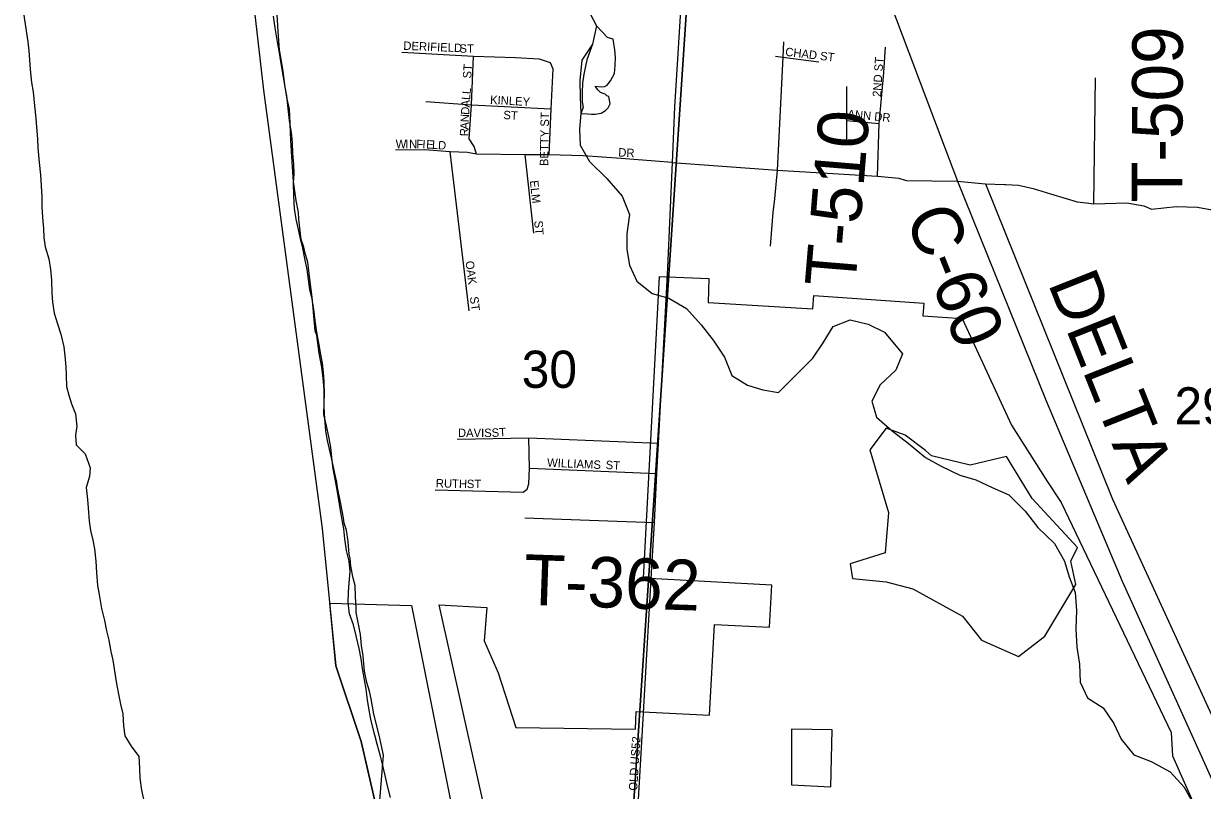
# Model space of a CAD drawing. Extents: x 1949938.81 to 1949945.61, y 152207.65 to 152214.09.
# Drawn here: x 1949939.542 to 1949940.868, y 152210.308 to 152211.171 of the extents above; entities that cross this region are included whole.
import ezdxf

# ---------------------------------------------------------------- set-up
doc = ezdxf.new("R2010")
doc.units = 0
for name, color, linetype in [('GM_X_City_Street', 7, 'Continuous'), ('GM_X_City_Street_Text', 7, 'Continuous'), ('GM_X_Corporation', 7, 'Continuous'), ('GM_X_County', 7, 'Continuous'), ('GM_X_County_Road', 7, 'Continuous'), ('GM_X_County_Road_Text', 7, 'Continuous'), ('GM_X_Major_River', 7, 'Continuous'), ('GM_X_Minor_Lake', 7, 'Continuous'), ('GM_X_Minor_River', 7, 'Continuous'), ('GM_X_Section', 7, 'Continuous'), ('GM_X_Section_Text', 7, 'Continuous'), ('GM_X_Township', 7, 'Continuous'), ('GM_X_Township_Road', 7, 'Continuous'), ('GM_X_Township_Road_Text', 7, 'Continuous'), ('GM_X_Township_Subdivision', 7, 'Continuous'), ('GM_X_Township_Subdivision_Text', 7, 'Continuous'), ('GM_X_US_Route', 7, 'Continuous')]:
    doc.layers.add(name, color=color, linetype=linetype)

msp = doc.modelspace()

# ---------------------------------------------------------------- linework, layer by layer
at = {"layer": 'GM_X_City_Street'}
msp.add_lwpolyline([(1949940.2381, 152210.3883), (1949940.2314, 152210.2719), (1949940.2281, 152210.2175)], dxfattribs=at)
at = {"layer": 'GM_X_Corporation'}
msp.add_lwpolyline([(1949940.0909, 152210.1498), (1949940.0091, 152210.5167), (1949940.0628, 152210.5138), (1949940.0597, 152210.4762), (1949940.0757, 152210.4401), (1949940.0953, 152210.3788), (1949940.2298, 152210.3768), (1949940.2308, 152210.3968), (1949940.3132, 152210.3927), (1949940.3187, 152210.4946), (1949940.3808, 152210.4915), (1949940.3834, 152210.5389), (1949940.2388, 152210.5466), (1949940.2569, 152210.8861), (1949940.3123, 152210.8839), (1949940.3118, 152210.857), (1949940.4294, 152210.8497), (1949940.4305, 152210.8648), (1949940.5542, 152210.8564), (1949940.5531, 152210.8419), (1949940.5973, 152210.8391), (1949940.6527, 152210.719), (1949940.6932, 152210.6552), (1949940.7087, 152210.632), (1949940.8323, 152210.3731), (1949940.8339, 152210.3468), (1949940.8851, 152210.231)], dxfattribs=at)
for points in [[(1949940.5118, 152210.7154), (1949940.4935, 152210.6912), (1949940.5147, 152210.6207), (1949940.5109, 152210.5753), (1949940.4713, 152210.5628), (1949940.4742, 152210.5463), (1949940.5118, 152210.5425), (1949940.5418, 152210.5347), (1949940.5978, 152210.5038), (1949940.619, 152210.4768), (1949940.6606, 152210.4584), (1949940.6905, 152210.4816), (1949940.7253, 152210.5396), (1949940.7195, 152210.5657), (1949940.7272, 152210.5811), (1949940.676, 152210.6362), (1949940.6472, 152210.6836), (1949940.6065, 152210.6739), (1949940.563, 152210.6845), (1949940.5563, 152210.6903), (1949940.5331, 152210.7077)], [(1949939.8861, 152210.5185), (1949939.9781, 152210.5158), (1949940.0249, 152210.2816), (1949940.1348, 152209.9064), (1949940.0387, 152209.8948), (1949939.9388, 152210.288), (1949939.9215, 152210.363), (1949939.8931, 152210.4482)], [(1949940.4054, 152210.3769), (1949940.4054, 152210.314), (1949940.4495, 152210.3118), (1949940.451, 152210.3762)]]:
    msp.add_lwpolyline(points, close=True, dxfattribs=at)
at = {"layer": 'GM_X_County'}
msp.add_lwpolyline([(1949939.7311, 152211.8376), (1949939.7258, 152211.7457), (1949939.7413, 152211.6273), (1949939.7962, 152211.2639), (1949939.7977, 152211.2171), (1949939.8117, 152211.0959), (1949939.8776, 152210.6025), (1949939.8931, 152210.4482), (1949939.9215, 152210.363), (1949939.9378, 152210.2911), (1949940.0851, 152209.7125), (1949940.1207, 152209.6209), (1949940.3383, 152209.2145), (1949940.3947, 152209.1158)], dxfattribs=at)
at = {"layer": 'GM_X_County_Road'}
for points in [[(1949940.0902, 152211.8474), (1949940.1245, 152211.7264), (1949940.1446, 152211.6586), (1949940.1553, 152211.6171), (1949940.1779, 152211.5675), (1949940.2141, 152211.4924), (1949940.2747, 152211.3627), (1949940.2807, 152211.3456), (1949940.2832, 152211.3349), (1949940.2845, 152211.32), (1949940.2871, 152211.2866), (1949940.2865, 152211.2628), (1949940.2824, 152211.2159), (1949940.2737, 152211.0767), (1949940.2714, 152211.0147), (1949940.2658, 152210.896)], [(1949940.6238, 152210.9905), (1949940.7663, 152210.6357), (1949940.884, 152210.3789), (1949940.9129, 152210.3457), (1949940.9292, 152210.3083), (1949940.9485, 152210.2329)], [(1949940.2658, 152210.896), (1949940.2627, 152210.8322), (1949940.2555, 152210.6987), (1949940.2536, 152210.6646), (1949940.2509, 152210.6092), (1949940.248, 152210.559)], [(1949940.248, 152210.559), (1949940.2393, 152210.4083)], [(1949940.2393, 152210.4083), (1949940.2381, 152210.3883)]]:
    msp.add_lwpolyline(points, dxfattribs=at)
at = {"layer": 'GM_X_Major_River'}
for points in [[(1949939.5418, 152211.1828), (1949939.5437, 152211.1703), (1949939.5452, 152211.16), (1949939.5467, 152211.1505), (1949939.5478, 152211.1403), (1949939.5486, 152211.13), (1949939.5493, 152211.1194), (1949939.5508, 152211.1046), (1949939.5524, 152211.0939), (1949939.5539, 152211.0784), (1949939.5554, 152211.0643), (1949939.5565, 152211.0544), (1949939.5576, 152211.0411), (1949939.558, 152211.0309), (1949939.5595, 152211.0146), (1949939.5607, 152211.0005), (1949939.5614, 152210.9883), (1949939.5622, 152210.9758), (1949939.5622, 152210.9652), (1949939.5629, 152210.9526), (1949939.5641, 152210.9401), (1949939.5644, 152210.9302), (1949939.5659, 152210.9196), (1949939.5701, 152210.9063), (1949939.572, 152210.8941), (1949939.5731, 152210.8823), (1949939.5735, 152210.8675), (1949939.5742, 152210.8573), (1949939.5761, 152210.8451), (1949939.5799, 152210.8329), (1949939.5837, 152210.8212), (1949939.5871, 152210.8071), (1949939.5882, 152210.7968), (1949939.5894, 152210.7847), (1949939.5897, 152210.7752), (1949939.5901, 152210.7623), (1949939.5928, 152210.7528), (1949939.5958, 152210.7429)], [(1949939.836, 152211.0992), (1949939.8341, 152211.1105), (1949939.8314, 152211.1261), (1949939.8292, 152211.1402), (1949939.8273, 152211.1504), (1949939.8246, 152211.166), (1949939.8227, 152211.1793)], [(1949939.9546, 152210.3), (1949939.9516, 152210.3114), (1949939.9485, 152210.3247), (1949939.9459, 152210.3357), (1949939.9432, 152210.3463), (1949939.9395, 152210.36), (1949939.9368, 152210.3699), (1949939.9327, 152210.3862), (1949939.9304, 152210.398), (1949939.9285, 152210.4098), (1949939.927, 152210.4216), (1949939.9251, 152210.4322), (1949939.9228, 152210.4452), (1949939.9213, 152210.4558), (1949939.9191, 152210.4676), (1949939.916, 152210.4817), (1949939.913, 152210.4942), (1949939.9085, 152210.5067), (1949939.907, 152210.5189), (1949939.9073, 152210.5315), (1949939.9081, 152210.5413), (1949939.9089, 152210.5543), (1949939.9081, 152210.5657), (1949939.9051, 152210.5778), (1949939.9032, 152210.5911), (1949939.9021, 152210.6022), (1949939.9002, 152210.6124), (1949939.8979, 152210.6253), (1949939.8964, 152210.6348), (1949939.8941, 152210.6481), (1949939.8922, 152210.658), (1949939.89, 152210.6698), (1949939.8888, 152210.6793), (1949939.8873, 152210.6938), (1949939.8851, 152210.7063), (1949939.8824, 152210.7181), (1949939.8794, 152210.731), (1949939.8798, 152210.7443), (1949939.8802, 152210.7538), (1949939.8798, 152210.7679), (1949939.879, 152210.7781), (1949939.8779, 152210.7888), (1949939.876, 152210.7983), (1949939.8741, 152210.8093), (1949939.8715, 152210.8237), (1949939.8696, 152210.8366), (1949939.8681, 152210.8496), (1949939.8662, 152210.8606), (1949939.8639, 152210.8716), (1949939.8624, 152210.883), (1949939.8609, 152210.894), (1949939.8582, 152210.9066), (1949939.856, 152210.918), (1949939.8533, 152210.9286), (1949939.8511, 152210.9392), (1949939.8484, 152210.9506), (1949939.8465, 152210.9628), (1949939.8458, 152210.9772), (1949939.8454, 152210.9913), (1949939.8462, 152211.0019), (1949939.8458, 152211.0125), (1949939.8447, 152211.0247), (1949939.8443, 152211.0369), (1949939.8431, 152211.0479), (1949939.8409, 152211.0619), (1949939.8394, 152211.0752), (1949939.8379, 152211.0897), (1949939.836, 152211.0992)], [(1949939.5958, 152210.7429), (1949939.6003, 152210.7315), (1949939.6018, 152210.7178), (1949939.6003, 152210.7075), (1949939.6011, 152210.6969), (1949939.6109, 152210.6866), (1949939.6166, 152210.671), (1949939.6158, 152210.6612), (1949939.612, 152210.6486), (1949939.6135, 152210.6353), (1949939.6143, 152210.6258), (1949939.6154, 152210.611), (1949939.6169, 152210.6003), (1949939.6196, 152210.5893), (1949939.6215, 152210.5798), (1949939.623, 152210.5657), (1949939.6237, 152210.5528), (1949939.6249, 152210.5384), (1949939.6268, 152210.5285), (1949939.6294, 152210.5125), (1949939.6328, 152210.4992), (1949939.6351, 152210.4874), (1949939.6377, 152210.4768), (1949939.64, 152210.4642), (1949939.6423, 152210.4544), (1949939.6438, 152210.4445), (1949939.646, 152210.43), (1949939.6483, 152210.4182), (1949939.6509, 152210.4049), (1949939.6536, 152210.3939), (1949939.654, 152210.3802), (1949939.6555, 152210.3692), (1949939.6627, 152210.3578), (1949939.6714, 152210.346), (1949939.6721, 152210.3327), (1949939.6725, 152210.3217), (1949939.6744, 152210.308), (1949939.6774, 152210.2947)]]:
    msp.add_lwpolyline(points, dxfattribs=at)
at = {"layer": 'GM_X_Minor_Lake'}
msp.add_line((1949940.1863, 152211.1684), (1949940.1817, 152211.1479), dxfattribs=at)
for points in [[(1949940.2063, 152211.1146), (1949940.2071, 152211.1237), (1949940.2074, 152211.1328), (1949940.2067, 152211.1412), (1949940.2048, 152211.1533), (1949940.1984, 152211.1552), (1949940.1863, 152211.1684)], [(1949940.1817, 152211.1479), (1949940.1753, 152211.1302), (1949940.1719, 152211.1139), (1949940.1704, 152211.104), (1949940.17, 152211.0934), (1949940.17, 152211.0828), (1949940.1711, 152211.0763), (1949940.1685, 152211.0696), (1949940.176, 152211.0695), (1949940.1806, 152211.0691), (1949940.1847, 152211.0691), (1949940.1915, 152211.0702), (1949940.1964, 152211.0729), (1949940.1991, 152211.0759), (1949940.2014, 152211.0804), (1949940.1999, 152211.0888), (1949940.1976, 152211.0896), (1949940.1957, 152211.0915), (1949940.1908, 152211.0934), (1949940.1878, 152211.0964), (1949940.1851, 152211.1002), (1949940.1851, 152211.1006), (1949940.1912, 152211.0998), (1949940.1953, 152211.1002), (1949940.1983, 152211.1017), (1949940.2018, 152211.1063), (1949940.2063, 152211.1146)]]:
    msp.add_lwpolyline(points, dxfattribs=at)
at = {"layer": 'GM_X_Minor_River'}
for points in [[(1949940.1751, 152211.1889), (1949940.1863, 152211.1684), (1949940.1817, 152211.1479), (1949940.1695, 152211.1297), (1949940.1672, 152211.1069), (1949940.1678, 152211.0886), (1949940.1685, 152211.0696), (1949940.1669, 152211.0522), (1949940.1676, 152211.0339), (1949940.1781, 152211.0156), (1949940.1978, 152210.9965), (1949940.2151, 152210.9767), (1949940.2233, 152210.9562), (1949940.2202, 152210.9341), (1949940.2202, 152210.9166), (1949940.2231, 152210.8991), (1949940.2314, 152210.8809), (1949940.2487, 152210.8671), (1949940.2676, 152210.8617), (1949940.2873, 152210.8502), (1949940.3039, 152210.8319), (1949940.3174, 152210.8144), (1949940.3302, 152210.7953), (1949940.3385, 152210.7748), (1949940.3559, 152210.764), (1949940.3733, 152210.7587), (1949940.3907, 152210.7555), (1949940.4295, 152210.7942), (1949940.4409, 152210.8116), (1949940.4523, 152210.8298), (1949940.4713, 152210.8374), (1949940.4917, 152210.8327), (1949940.5099, 152210.8235), (1949940.5302, 152210.7991), (1949940.5226, 152210.7809), (1949940.5051, 152210.7642), (1949940.4959, 152210.746), (1949940.5011, 152210.7278), (1949940.5185, 152210.7125), (1949940.5366, 152210.6987), (1949940.5562, 152210.6827), (1949940.5736, 152210.6727), (1949940.5948, 152210.6628), (1949940.6129, 152210.6574), (1949940.6311, 152210.6489), (1949940.65, 152210.6405), (1949940.6681, 152210.6222), (1949940.6824, 152210.6039), (1949940.7013, 152210.5856), (1949940.7125, 152210.5658), (1949940.7178, 152210.5482), (1949940.7245, 152210.5307), (1949940.7259, 152210.5102)], [(1949940.7259, 152210.5102), (1949940.7251, 152210.4897), (1949940.7265, 152210.4691), (1949940.7295, 152210.4501), (1949940.7302, 152210.4296), (1949940.7384, 152210.412), (1949940.7558, 152210.4006), (1949940.7678, 152210.383), (1949940.7761, 152210.3655), (1949940.7904, 152210.348), (1949940.8101, 152210.3403), (1949940.8312, 152210.3288), (1949940.8471, 152210.3113), (1949940.8569, 152210.2937)]]:
    msp.add_lwpolyline(points, dxfattribs=at)
at = {"layer": 'GM_X_Section'}
for points in [[(1949940.2943, 152211.2945), (1949940.227, 152210.2792)], [(1949939.9424, 152210.2964), (1949939.9466, 152210.3476), (1949939.9417, 152210.3699), (1949939.9357, 152210.3938), (1949939.9327, 152210.4109), (1949939.9308, 152210.4196), (1949939.9278, 152210.4294), (1949939.9251, 152210.4419), (1949939.9236, 152210.4594), (1949939.9217, 152210.4711), (1949939.9206, 152210.4832), (1949939.9187, 152210.4931), (1949939.9157, 152210.5082), (1949939.9157, 152210.5135), (1949939.9149, 152210.526), (1949939.9146, 152210.5386), (1949939.9123, 152210.5469), (1949939.9097, 152210.5602), (1949939.9089, 152210.5689), (1949939.9078, 152210.5738), (1949939.907, 152210.5878), (1949939.9051, 152210.6007), (1949939.9025, 152210.6087), (1949939.9014, 152210.6147), (1949939.8987, 152210.6302), (1949939.8949, 152210.6488), (1949939.8942, 152210.6549), (1949939.8923, 152210.6632), (1949939.8881, 152210.6822), (1949939.8836, 152210.7015), (1949939.8817, 152210.7125), (1949939.8806, 152210.7261), (1949939.8798, 152210.7394), (1949939.8799, 152210.7591), (1949939.8787, 152210.772), (1949939.8772, 152210.7841), (1949939.8742, 152210.8), (1949939.8716, 152210.8197), (1949939.8697, 152210.825), (1949939.8689, 152210.8337), (1949939.8663, 152210.8629), (1949939.8636, 152210.8834), (1949939.8614, 152210.9023), (1949939.8587, 152210.911), (1949939.8569, 152210.9194), (1949939.8538, 152210.9277), (1949939.8531, 152210.9341), (1949939.8512, 152210.9508), (1949939.8508, 152210.9584), (1949939.8482, 152210.9717), (1949939.8467, 152210.9823), (1949939.8455, 152210.9932), (1949939.8437, 152211.0148), (1949939.8422, 152211.0395), (1949939.8414, 152211.0671), (1949939.8407, 152211.0747), (1949939.8384, 152211.0861), (1949939.8358, 152211.0993), (1949939.8339, 152211.1175), (1949939.8316, 152211.1308), (1949939.8297, 152211.1414), (1949939.8282, 152211.1619), (1949939.8267, 152211.1872)]]:
    msp.add_lwpolyline(points, dxfattribs=at)
msp.add_lwpolyline([(1949941.3926, 152211.2226), (1949941.3344, 152210.2133), (1949940.227, 152210.2792), (1949940.2943, 152211.2945)], close=True, dxfattribs=at)
at = {"layer": 'GM_X_Township'}
msp.add_lwpolyline([(1949939.7311, 152211.8376), (1949939.7258, 152211.7457), (1949939.7413, 152211.6273), (1949939.7962, 152211.2639), (1949939.7977, 152211.2171), (1949939.8117, 152211.0959), (1949939.8776, 152210.6025), (1949939.8931, 152210.4482), (1949939.9215, 152210.363), (1949939.9378, 152210.2911), (1949940.0851, 152209.7125), (1949940.1207, 152209.6209), (1949940.3383, 152209.2145), (1949940.3947, 152209.1158)], dxfattribs=at)
at = {"layer": 'GM_X_Township_Road'}
for points in [[(1949940.3966, 152211.1504), (1949940.3958, 152211.1332), (1949940.3895, 152211.006), (1949940.3862, 152210.9735)], [(1949940.7456, 152210.9681), (1949940.7473, 152211.11)], [(1949940.2714, 152211.0147), (1949940.3895, 152211.006), (1949940.5023, 152210.999), (1949940.5262, 152210.997), (1949940.5331, 152210.9947)], [(1949940.5331, 152210.9947), (1949940.5348, 152210.9941), (1949940.5634, 152210.9939)], [(1949940.5634, 152210.9939), (1949940.5921, 152210.9937), (1949940.6037, 152210.9925)], [(1949940.6037, 152210.9925), (1949940.6238, 152210.9905), (1949940.6449, 152210.9899)], [(1949940.6449, 152210.9899), (1949940.6466, 152210.9899), (1949940.6606, 152210.9891), (1949940.6771, 152210.9853), (1949940.6968, 152210.9791), (1949940.7145, 152210.9739), (1949940.7267, 152210.9702), (1949940.7369, 152210.9691)], [(1949940.3862, 152210.9735), (1949940.3846, 152210.9583), (1949940.3815, 152210.9205)], [(1949940.7369, 152210.9691), (1949940.7456, 152210.9681), (1949940.7827, 152210.969), (1949940.8017, 152210.9656), (1949940.8103, 152210.9621), (1949940.8382, 152210.9649), (1949940.862, 152210.9642), (1949940.8762, 152210.9618), (1949940.8859, 152210.9587), (1949940.8979, 152210.9521), (1949940.9124, 152210.9386), (1949940.9317, 152210.9238), (1949940.96, 152210.9083), (1949940.9794, 152210.9086), (1949940.9904, 152210.909), (1949941.0118, 152210.9124), (1949941.0332, 152210.9203)], [(1949940.1057, 152210.6145), (1949940.2509, 152210.6092)]]:
    msp.add_lwpolyline(points, dxfattribs=at)
at = {"layer": 'GM_X_Township_Subdivision'}
for points in [[(1949940.5093, 152211.1154), (1949940.5094, 152211.116), (1949940.5112, 152211.1445)], [(1949939.9671, 152211.1386), (1949940.0478, 152211.1344), (1949940.0949, 152211.1326), (1949940.1217, 152211.1311), (1949940.1342, 152211.1272)], [(1949940.0512, 152211.024), (1949940.0484, 152211.0327), (1949940.043, 152211.041), (1949940.0457, 152211.0795), (1949940.0478, 152211.1344)], [(1949940.3875, 152211.1343), (1949940.3958, 152211.1332), (1949940.4361, 152211.1278)], [(1949940.1342, 152211.1272), (1949940.1369, 152211.1201), (1949940.1348, 152211.075), (1949940.1325, 152211.023)], [(1949940.5023, 152210.999), (1949940.5042, 152211.0584), (1949940.5093, 152211.1154)], [(1949940.4672, 152211.1), (1949940.4672, 152211.0618), (1949940.4672, 152211.0409)], [(1949939.9941, 152211.0831), (1949940.0457, 152211.0795), (1949940.1348, 152211.075)], [(1949940.4672, 152211.0618), (1949940.5042, 152211.0584)], [(1949940.2714, 152211.0147), (1949940.2137, 152211.0192), (1949940.1713, 152211.0221), (1949940.1325, 152211.023), (1949940.1054, 152211.023), (1949940.0512, 152211.024), (1949940.0409, 152211.0258), (1949940.0214, 152211.0267), (1949939.9926, 152211.0289), (1949939.9601, 152211.0285)], [(1949940.043, 152210.8476), (1949940.0214, 152211.0267)], [(1949940.1054, 152211.023), (1949940.1153, 152210.9351)], [(1949940.0045, 152210.646), (1949940.1038, 152210.6436), (1949940.1083, 152210.6469), (1949940.1099, 152210.653), (1949940.1106, 152210.6705), (1949940.1102, 152210.7046)], [(1949940.0295, 152210.703), (1949940.1102, 152210.7046), (1949940.2555, 152210.6987)], [(1949940.1106, 152210.6705), (1949940.2536, 152210.6646)]]:
    msp.add_lwpolyline(points, dxfattribs=at)
at = {"layer": 'GM_X_US_Route'}
msp.add_lwpolyline([(1949940.448, 152211.375), (1949940.4583, 152211.3469), (1949940.5043, 152211.2261), (1949940.5628, 152211.0708), (1949940.5921, 152210.9937), (1949940.6917, 152210.7462), (1949940.7773, 152210.5432), (1949940.8719, 152210.3344), (1949940.9687, 152210.1169), (1949941.0372, 152209.9608), (1949941.0687, 152209.891)], dxfattribs=at)

# ---------------------------------------------------------------- texts
at = {"layer": 'GM_X_City_Street_Text'}
msp.add_text('OLD US52', height=0.00947, rotation=86.369, dxfattribs=at).set_placement((1949940.2318, 152210.3072))
at = {"layer": 'GM_X_County_Road_Text'}
for s, rotation, p in [('C-60', 291.8015, (1949940.5328, 152210.9538)), ('DELTA', 291.685, (1949940.6934, 152210.8787))]:
    msp.add_text(s, height=0.05682, rotation=rotation, dxfattribs=at).set_placement(p)
at = {"layer": 'GM_X_Section_Text'}
for s, p in [('30', (1949940.102, 152210.7609)), ('29', (1949940.8361, 152210.7197))]:
    msp.add_text(s, height=0.04186, rotation=0, dxfattribs=at).set_placement(p)
at = {"layer": 'GM_X_Township_Road_Text'}
for s, rotation, p in [('T-509', 89.7193, (1949940.8447, 152210.9691)), ('T-510', 85.2833, (1949940.477, 152210.873)), ('T-362', 358.0347, (1949940.1036, 152210.5169))]:
    msp.add_text(s, height=0.05682, rotation=rotation, dxfattribs=at).set_placement(p)
at = {"layer": 'GM_X_Township_Subdivision_Text'}
for s, rotation, p in [('DERIFIELD', 357.6138, (1949939.9687, 152211.1414)), ('ST', 0, (1949940.032, 152211.1381)), ('CHAD ST', 353.2336, (1949940.398, 152211.1347)), ('2ND ST', 86.3495, (1949940.506, 152211.0881)), ('ST', 86.4257, (1949940.0452, 152211.1089)), ('L', 85.2956, (1949940.0439, 152211.0846)), ('L', 85.2409, (1949940.0445, 152211.0912)), ('A', 86.0845, (1949940.0434, 152211.0763)), ('KINLEY', 356.6977, (1949940.0662, 152211.0806)), ('N', 87.3357, (1949940.0426, 152211.0597)), ('D', 87.3325, (1949940.043, 152211.068)), ('ST', 356.4228, (1949940.0811, 152211.0635)), ('BETTY ST', 89.0911, (1949940.1318, 152211.0105)), ('ANN DR', 354.6107, (1949940.468, 152211.0647)), ('R', 87.3277, (1949940.0418, 152211.0439)), ('A', 87.3107, (1949940.0422, 152211.0514)), ('W', 359.9664, (1949939.9603, 152211.0306)), ('I', 359.9616, (1949939.9711, 152211.0306)), ('N', 359.9673, (1949939.9753, 152211.0306)), ('F', 359.819, (1949939.9836, 152211.0306)), ('I', 358.12, (1949939.9902, 152211.0305)), ('E', 356.4458, (1949939.9943, 152211.0304)), ('L', 355.9227, (1949940.0009, 152211.03)), ('D', 355.9152, (1949940.0076, 152211.0295)), ('DR', 356.987, (1949940.2104, 152211.0214)), ('ELM', 275.9104, (1949940.1112, 152210.994)), ('ST', 273.5744, (1949940.1162, 152210.9489)), ('OAK', 277.5905, (1949940.0387, 152210.9032)), ('ST', 277.1347, (1949940.0437, 152210.8632)), ('DAVIS', 0, (1949940.0303, 152210.7056)), ('ST', 3.5763, (1949940.0685, 152210.7056)), ('WILLIAMS', 357.5106, (1949940.1304, 152210.6722)), ('ST', 356.4237, (1949940.1962, 152210.6697)), ('RUTH', 358.4928, (1949940.0053, 152210.6489)), ('ST', 0, (1949940.0403, 152210.6481))]:
    msp.add_text(s, height=0.00947, rotation=rotation, dxfattribs=at).set_placement(p)

doc.saveas('drawing.dxf')
